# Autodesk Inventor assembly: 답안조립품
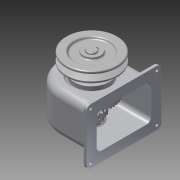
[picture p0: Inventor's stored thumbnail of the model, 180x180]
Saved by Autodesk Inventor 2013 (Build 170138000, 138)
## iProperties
Created: 2016-01
Part Number: 답안조립품
Document SubType Name: Assembly
Designer: dgall
Author: dgall
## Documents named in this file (16)
- C:\Users\dgall\Desktop\답안조립품.iam
- C:\Users\dgall\Desktop\본체.ipt
- C:\Users\dgall\Desktop\460105V1013\V-벨트풀리.ipt
- C:\Users\dgall\Desktop\460105V1013\뒤커버.ipt
- C:\Users\dgall\Desktop\460105V1013\멈춤나사 - M4x10.ipt
- C:\Users\dgall\Desktop\460105V1013\베어링 6203.ipt
- C:\Users\dgall\Desktop\460105V1013\볼트 M3 x 8.ipt
- C:\Users\dgall\Desktop\460105V1013\볼트 M3 x 10.ipt
- C:\Users\dgall\Desktop\460105V1013\부시1.ipt
- C:\Users\dgall\Desktop\460105V1013\부시2.ipt
- C:\Users\dgall\Desktop\460105V1013\스퍼기어.ipt
- C:\Users\dgall\Desktop\460105V1013\앞커버.ipt
- C:\Users\dgall\Desktop\460105V1013\오일씰 28 40 8.ipt
- C:\Users\dgall\Desktop\460105V1013\축.ipt
- C:\Users\dgall\Desktop\460105V1013\키 - 5 x 5 x 18.ipt
- C:\Users\dgall\Desktop\460105V1013\키 - 6 x 6 x 22.ipt
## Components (9 placed, 3 different names)
1. V-벨트풀리:1 — 플러쉬:1
2. ISO 4762 M3 x 8:1 — 플러쉬:2
3. ISO 4762 M3 x 10:1 — 플러쉬:9
4. ISO 4762 M3 x 8:2 — 플러쉬:5
5. ISO 4762 M3 x 8:3 — 플러쉬:3
6. ISO 4762 M3 x 8:4 — 플러쉬:4
7. ISO 4762 M3 x 10:2 — 플러쉬:8
8. ISO 4762 M3 x 10:3 — 플러쉬:7
9. ISO 4762 M3 x 10:4 — 플러쉬:6
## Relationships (9: Flush 9)
- 플러쉬:1 [Flush]: V-벨트풀리:1
- 플러쉬:2 [Flush]: ISO 4762 M3 x 8:1
- 플러쉬:3 [Flush]: ISO 4762 M3 x 8:3
- 플러쉬:4 [Flush]: ISO 4762 M3 x 8:4
- 플러쉬:5 [Flush]: ISO 4762 M3 x 8:2
- 플러쉬:6 [Flush]: ISO 4762 M3 x 10:4
- 플러쉬:7 [Flush]: ISO 4762 M3 x 10:3
- 플러쉬:8 [Flush]: ISO 4762 M3 x 10:2
- 플러쉬:9 [Flush]: ISO 4762 M3 x 10:1
